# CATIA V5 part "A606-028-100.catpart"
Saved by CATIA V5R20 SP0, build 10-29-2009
Part number: A606-028-100
Source: Unknown
Property "ARTICLENO": "A606-028-100"
Property "BOMINFO": "A606-028-100"
Property "CODE": "A606-028-100"
Property "HOLES": "2"
Property "L": "100.000"
Property "L1": "25.000"
Property "L2": "50.000"
Property "LINA": "A606-028-100"
Property "NB": "A606-028-100"
Property "NBSYN": "$CODE."
Property "NN": "A606"
Property "NT": "Wear Plates, self-lubricating"
Property "SCREW": "2xM6"
Property "SUPPLIER": "CF"
Property "W": "28.000"
Bounding box of the stored display mesh (mm): x -14 to 14, y -5 to 5, z -50 to 50
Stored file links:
  C:\Users\Utente\Desktop\3D files A606\A606-028-100.catpart
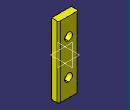
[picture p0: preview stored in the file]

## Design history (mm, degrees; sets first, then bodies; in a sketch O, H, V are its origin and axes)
Body1 "Geometry.1" (main body)
  Solid1 "A606-028-100.catpart": solid without history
